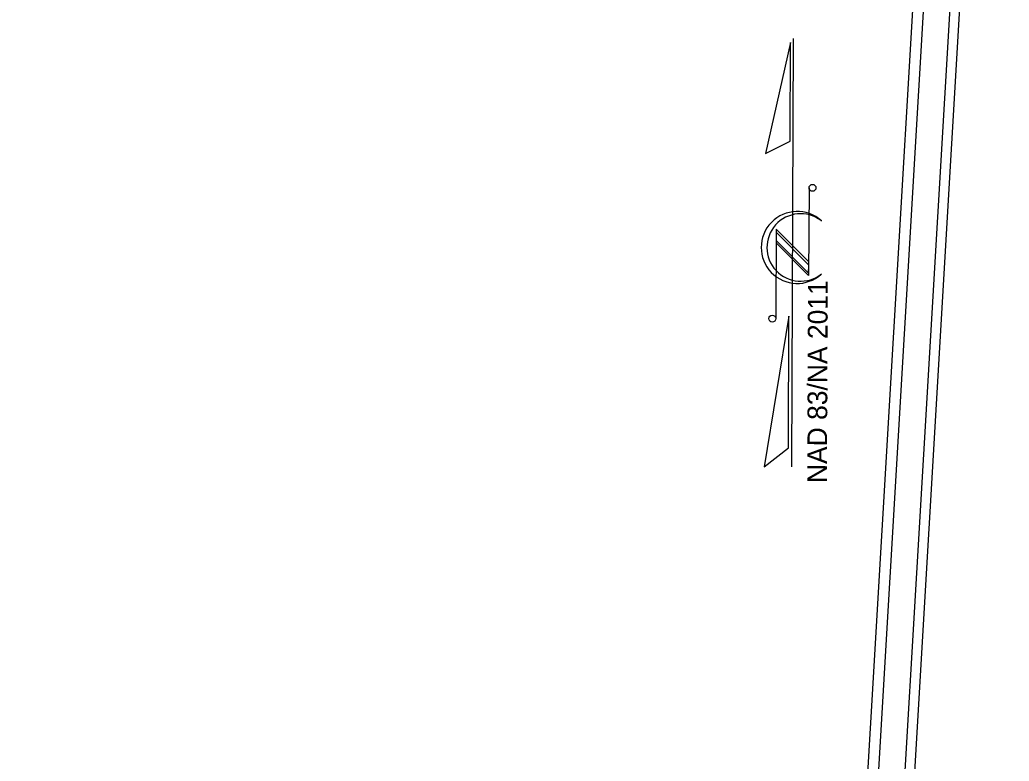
# Model space of a CAD drawing. Extents: x 1998567 to 2027801, y 439108 to 451079.
# Drawn here: x 2016563 to 2021220, y 442597 to 446086 of the extents above; entities that cross this region are included whole.
import ezdxf

# ---------------------------------------------------------------- set-up
doc = ezdxf.new("R2010")
doc.units = 0
for name, color, linetype in [('Sheet North Arrow CELL', 7, 'Continuous'), ('Sheet Plot Border Inside CELL', 7, 'Continuous'), ('Sheet Plot Border Outside CELL', 7, 'Continuous'), ('Sheet Title CELL', 7, 'Continuous')]:
    doc.layers.add(name, color=color, linetype=linetype)

msp = doc.modelspace()

# ---------------------------------------------------------------- linework, layer by layer
at = {"layer": 'Sheet North Arrow CELL'}
for p, q in [((2020197, 443981.6), (2020204.6, 445997.3)), ((2020278, 445295.6), (2020276.4, 444881.9)), ((2020123.1, 445101.1), (2020121.5, 444680.6)), ((2020276.6, 444946.4), (2020123.1, 445101.1)), ((2020334.4, 445141.2), (2020336.6, 445139.7)), ((2020123, 445085.9), (2020122.9, 445048.1)), ((2020276.6, 444931.2), (2020123, 445085.9)), ((2020276.4, 444881.9), (2020122.8, 445036.6)), ((2020276.4, 444893.3), (2020122.9, 445048.1)), ((2020122.9, 445048.1), (2020276.4, 444893.3)), ((2020276.4, 444893.3), (2020276.6, 444931.2))]:
    msp.add_line(p, q, dxfattribs=at)
for points in [[(2020190.6, 445979.7), (2020073.6, 445456.7), (2020188.8, 445514.5)], [(2020183.2, 444691.8), (2020066.4, 443982.1), (2020180.9, 444071.6)]]:
    msp.add_lwpolyline(points, close=True, dxfattribs=at)
for centre in [(2020294.4, 445295.2), (2020105.1, 444680)]:
    msp.add_circle(centre, 16.4, dxfattribs=at)
for centre, radius, start, end in [((2020222.3, 445014.6), 169.3, 47.622, 312.176), ((2020238.7, 445014.6), 158.7, 52.877, 308.4107)]:
    msp.add_arc(centre, radius, start, end, dxfattribs=at)
at = {"layer": 'Sheet Plot Border Inside CELL'}
msp.add_lwpolyline([(2003905.2, 440314.9), (2020541.3, 439334.2), (2021162.2, 449866.9), (2004526.1, 450847.6)], close=True, dxfattribs=at)
at = {"layer": 'Sheet Plot Border Outside CELL'}
msp.add_lwpolyline([(2021220.3, 450088.4), (2004409.5, 451079.4), (2003762.2, 440098.6), (2020573, 439107.6)], close=True, dxfattribs=at)
at = {"layer": 'Sheet Title CELL'}
for points in [[(2020423.9, 439467), (2021030, 449749)], [(2020485.8, 441366.5), (2020977.2, 449702.2)]]:
    msp.add_lwpolyline(points, dxfattribs=at)

# ---------------------------------------------------------------- texts
at = {"layer": 'Sheet North Arrow CELL'}
msp.add_text('NAD 83/NA 2011', height=93.036, rotation=89.782, dxfattribs=at).set_placement((2020362.6, 443905.6))

doc.saveas('drawing.dxf')
